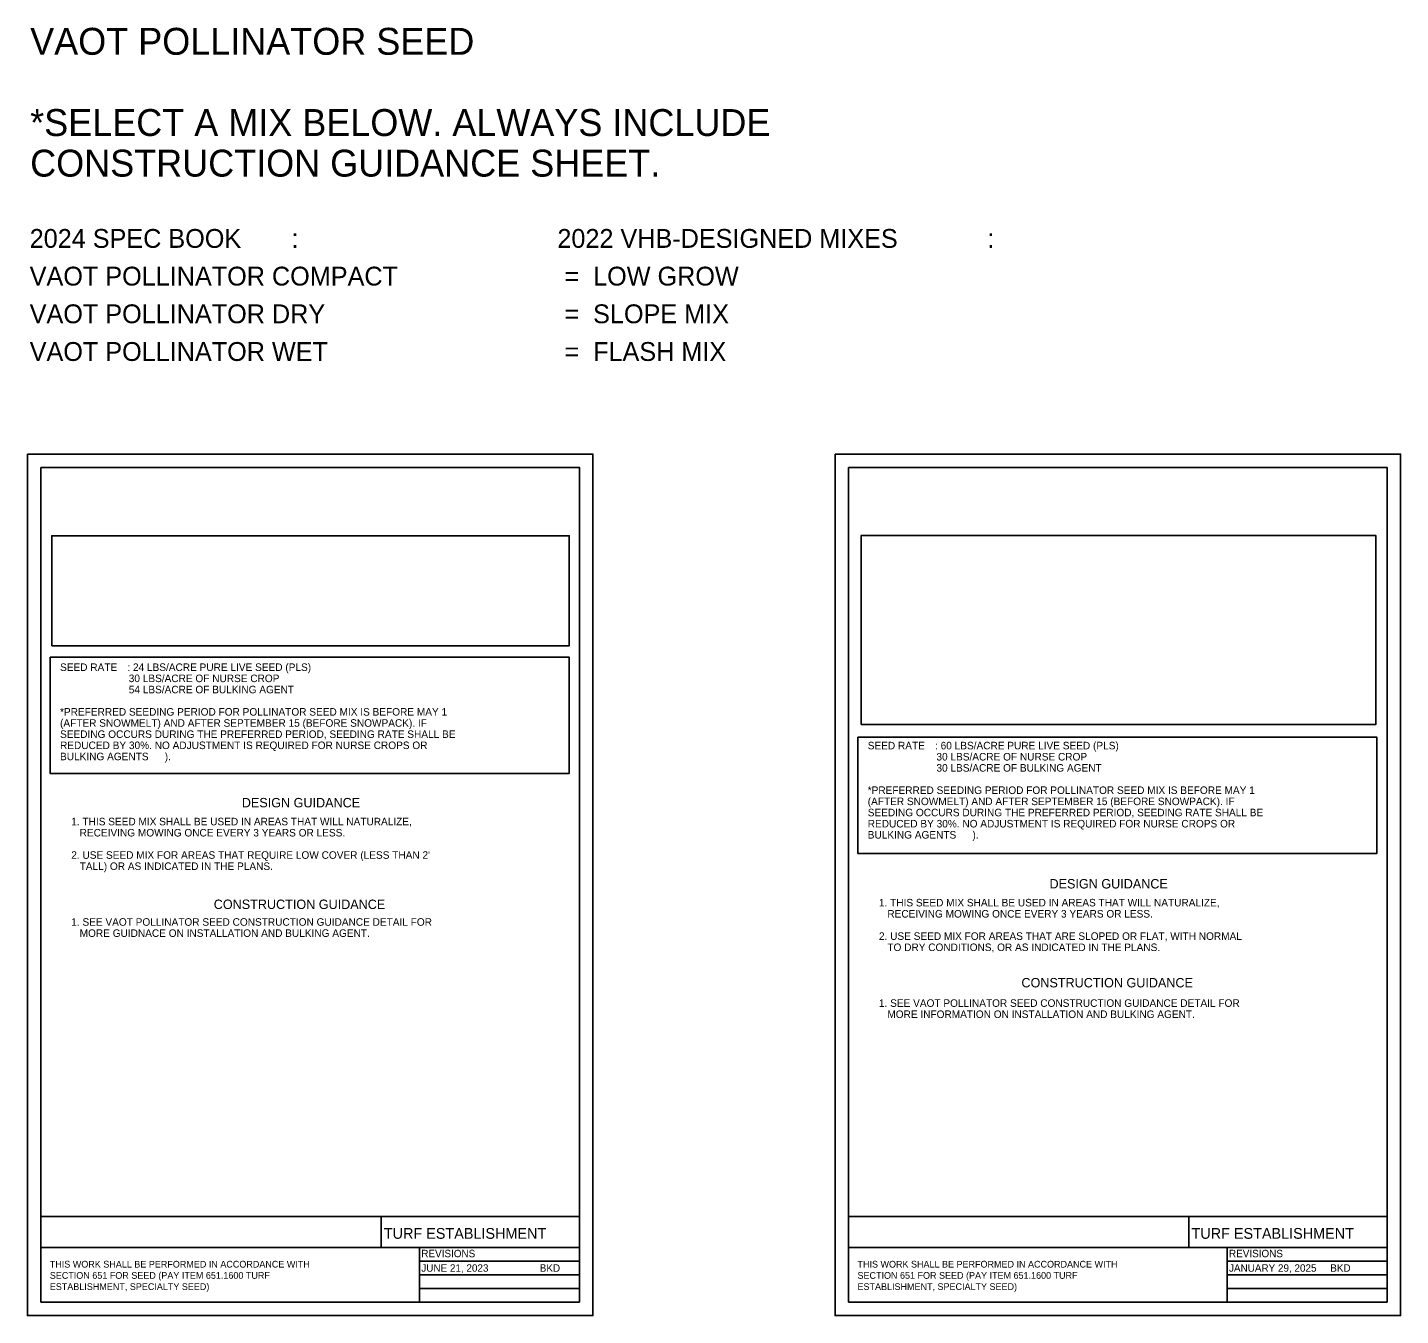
# Model space of a CAD drawing. Extents: x 900 to 2010, y -766 to -287.
# Drawn here: x 900 to 1410, y -766 to -287 of the extents above; entities that cross this region are included whole.
import ezdxf

# ---------------------------------------------------------------- set-up
doc = ezdxf.new("R2010")
doc.units = 0
for name, color, linetype in [('NBC1', 7, 'Continuous'), ('NBL1', 7, 'Continuous'), ('NBL1_T', 7, 'Continuous'), ('NBLNC1', 7, 'Continuous')]:
    doc.layers.add(name, color=color, linetype=linetype)

msp = doc.modelspace()

# ---------------------------------------------------------------- linework, layer by layer
at = {"layer": 'NBC1'}
for points in [[(900, -445.85), (1110, -445.85), (1110, -765.85), (900, -765.85)], [(1200, -445.85), (1410, -445.85), (1410, -765.85), (1200, -765.85)]]:
    msp.add_lwpolyline(points, close=True, dxfattribs=at)
at = {"layer": 'NBL1'}
for p, q in [((1031.4, -729.01), (1031.4, -740.54)), ((1331.4, -729.01), (1331.4, -740.54)), ((1105, -740.54), (905, -740.54)), ((1405, -740.54), (1205, -740.54))]:
    msp.add_line(p, q, dxfattribs=at)
for points in [[(905, -450.85), (1105, -450.85), (1105, -760.85), (905, -760.85)], [(1205, -450.85), (1405, -450.85), (1405, -760.85), (1205, -760.85)]]:
    msp.add_lwpolyline(points, close=True, dxfattribs=at)
for points in [[(1105, -729.01), (905, -729.01)], [(1405, -729.01), (1205, -729.01)]]:
    msp.add_lwpolyline(points, dxfattribs=at)
at = {"layer": 'NBL1_T'}
for points in [[(909, -517.04), (1101.22, -517.04), (1101.22, -476.24), (909, -476.24)], [(1209.72, -546.36), (1400.77, -546.36), (1400.77, -476.1), (1209.72, -476.1)], [(908.48, -521.29), (1101.15, -521.29), (1101.15, -564.55), (908.48, -564.55)], [(1208.48, -551.02), (1401.15, -551.02), (1401.15, -594.28), (1208.48, -594.28)]]:
    msp.add_lwpolyline(points, close=True, dxfattribs=at)
at = {"layer": 'NBLNC1'}
for points in [[(1045.64, -740.54), (1105, -740.54), (1105, -745.62), (1045.64, -745.62)], [(1345.64, -740.54), (1405, -740.54), (1405, -745.62), (1345.64, -745.62)], [(1045.64, -745.62), (1105, -745.62), (1105, -750.69), (1045.64, -750.69)], [(1345.64, -745.62), (1405, -745.62), (1405, -750.69), (1345.64, -750.69)], [(1045.64, -750.69), (1105, -750.69), (1105, -755.77), (1045.64, -755.77)], [(1345.64, -750.69), (1405, -750.69), (1405, -755.77), (1345.64, -755.77)], [(1045.64, -755.77), (1105, -755.77), (1105, -760.85), (1045.64, -760.85)], [(1345.64, -755.77), (1405, -755.77), (1405, -760.85), (1345.64, -760.85)]]:
    msp.add_lwpolyline(points, close=True, dxfattribs=at)

# ---------------------------------------------------------------- texts
at = {"layer": 'NBL1_T'}
for s, height, p in [('2024 SPEC BOOK', 7, (900.83, -369.28)), (':', 7, (998.06, -369.28)), ('2022 VHB-DESIGNED MIXES', 7, (1096.83, -369.28)), (':', 7, (1256.56, -369.28)), ('VAOT POLLINATOR COMPACT', 7, (900.83, -383.28)), (' =  LOW GROW', 7, (1096.83, -383.28)), ('VAOT POLLINATOR DRY', 7, (900.83, -397.28)), (' =  SLOPE MIX', 7, (1096.83, -397.28)), ('VAOT POLLINATOR WET', 7, (900.83, -411.28)), (' =  FLASH MIX', 7, (1096.83, -411.28)), ('TURF ESTABLISHMENT', 4, (1032.36, -737.34)), ('TURF ESTABLISHMENT', 4, (1332.36, -737.34)), ('THIS WORK SHALL BE PERFORMED IN ACCORDANCE WITH ', 2.5, (908.3, -748.03)), ('SECTION 651 FOR SEED (PAY ITEM 651.1600 TURF ', 2.5, (908.3, -752.2)), ('THIS WORK SHALL BE PERFORMED IN ACCORDANCE WITH ', 2.5, (1208.3, -748.03)), ('SECTION 651 FOR SEED (PAY ITEM 651.1600 TURF ', 2.5, (1208.3, -752.2)), ('ESTABLISHMENT, SPECIALTY SEED)', 2.5, (908.3, -756.36)), ('ESTABLISHMENT, SPECIALTY SEED)', 2.5, (1208.3, -756.36))]:
    msp.add_text(s, height=height, dxfattribs=at).set_placement(p)
at = {"layer": 'NBLNC1'}
for s, height, p in [('VAOT POLLINATOR SEED', 10, (901.01, -297.57)), ('*SELECT A MIX BELOW. ALWAYS INCLUDE ', 10, (901.01, -327.74)), ('CONSTRUCTION GUIDANCE SHEET.', 10, (901.01, -342.82)), ('SEED RATE', 2.8, (912.1, -526.44)), (': 24 LBS/ACRE PURE LIVE SEED (PLS) ', 2.8, (937.1, -526.44)), ('   30 LBS/ACRE OF NURSE CROP', 2.8, (934.5, -530.58)), ('   54 LBS/ACRE OF BULKING AGENT', 2.8, (934.5, -534.73)), ('*PREFERRED SEEDING PERIOD FOR POLLINATOR SEED MIX IS BEFORE MAY 1 ', 2.8, (912.1, -543.02)), ('(AFTER SNOWMELT) AND AFTER SEPTEMBER 15 (BEFORE SNOWPACK). IF ', 2.8, (912.1, -547.16)), ('SEEDING OCCURS DURING THE PREFERRED PERIOD, SEEDING RATE SHALL BE ', 2.8, (912.1, -551.31)), ('REDUCED BY 30%. NO ADJUSTMENT IS REQUIRED FOR NURSE CROPS OR ', 2.8, (912.1, -555.45)), ('SEED RATE', 2.8, (1212.1, -555.55)), (': 60 LBS/ACRE PURE LIVE SEED (PLS) ', 2.8, (1237.1, -555.55)), ('BULKING AGENTS', 2.8, (912.1, -559.6)), (').', 2.8, (950.99, -559.6)), ('   30 LBS/ACRE OF NURSE CROP', 2.8, (1234.5, -559.69)), ('   30 LBS/ACRE OF BULKING AGENT', 2.8, (1234.5, -563.83)), ('*PREFERRED SEEDING PERIOD FOR POLLINATOR SEED MIX IS BEFORE MAY 1 ', 2.8, (1212.1, -572.12)), ('DESIGN GUIDANCE', 3.5, (979.62, -577.1)), ('(AFTER SNOWMELT) AND AFTER SEPTEMBER 15 (BEFORE SNOWPACK). IF ', 2.8, (1212.1, -576.27)), ('1. THIS SEED MIX SHALL BE USED IN AREAS THAT WILL NATURALIZE, ', 2.8, (916.27, -583.77)), ('SEEDING OCCURS DURING THE PREFERRED PERIOD, SEEDING RATE SHALL BE ', 2.8, (1212.1, -580.41)), ('   RECEIVING MOWING ONCE EVERY 3 YEARS OR LESS.', 2.8, (916.27, -587.91)), ('REDUCED BY 30%. NO ADJUSTMENT IS REQUIRED FOR NURSE CROPS OR ', 2.8, (1212.1, -584.56)), ('BULKING AGENTS', 2.8, (1212.1, -588.7)), (').', 2.8, (1250.99, -588.7)), ("2. USE SEED MIX FOR AREAS THAT REQUIRE LOW COVER (LESS THAN 2' ", 2.8, (916.27, -596.2)), ('   TALL) OR AS INDICATED IN THE PLANS.', 2.8, (916.27, -600.35)), ('DESIGN GUIDANCE', 3.5, (1279.62, -607.22)), ('CONSTRUCTION GUIDANCE', 3.5, (969.2, -614.85)), ('1. THIS SEED MIX SHALL BE USED IN AREAS THAT WILL NATURALIZE, ', 2.8, (1216.27, -613.89)), ('   RECEIVING MOWING ONCE EVERY 3 YEARS OR LESS.', 2.8, (1216.27, -618.03)), ('1. SEE VAOT POLLINATOR SEED CONSTRUCTION GUIDANCE DETAIL FOR ', 2.8, (916.27, -621.07)), ('   MORE GUIDNACE ON INSTALLATION AND BULKING AGENT.', 2.8, (916.27, -625.21)), ('2. USE SEED MIX FOR AREAS THAT ARE SLOPED OR FLAT, WITH NORMAL ', 2.8, (1216.27, -626.32)), ('   TO DRY CONDITIONS, OR AS INDICATED IN THE PLANS.', 2.8, (1216.27, -630.47)), ('CONSTRUCTION GUIDANCE', 3.5, (1269.2, -643.97)), ('1. SEE VAOT POLLINATOR SEED CONSTRUCTION GUIDANCE DETAIL FOR ', 2.8, (1216.27, -651.19)), ('   MORE INFORMATION ON INSTALLATION AND BULKING AGENT.', 2.8, (1216.27, -655.33)), ('REVISIONS', 2.75, (1046.29, -744.19)), ('REVISIONS', 2.75, (1346.29, -744.19)), ('JUNE 21, 2023   ', 2.75, (1046.29, -749.57)), ('BKD', 2.75, (1090.29, -749.57)), ('JANUARY 29, 2025     BKD', 2.75, (1346.29, -749.57))]:
    msp.add_text(s, height=height, dxfattribs=at).set_placement(p)

doc.saveas('drawing.dxf')
